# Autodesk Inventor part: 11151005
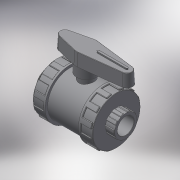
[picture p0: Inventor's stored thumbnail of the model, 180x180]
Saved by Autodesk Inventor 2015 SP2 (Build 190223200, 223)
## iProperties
Created: 2017-11
Part Number: 11151005
Material: Generic
Description: 2/NUT VALVE FEMALE THREAD 1/2" PVC
Document SubType Name: Modeling
Designer: KIM
Density: 1 g/cm^3
Appearance: Default
Author: KIM
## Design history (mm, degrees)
derived "111510.ipt"
feature "Solid1::111510.ipt"
tag "TaggingFeature1"
body "Solid1"
other parameters: "d0" = 75, "d1" = 18.631, "d2" = 45, "d3" = 15, "d4" = 14.9048, "d5" = 10.5, "d7" = 26.0834, "d8" = 40.5, "d13" = 0.55893, "d23" = 15, "d24" = 43.2, "d25" = 0.37262, "d26" = 0.55893, "d27" = 6.75, "d28" = 3.375, "d29" = 11.25, "d30" = 0, "d35" = 0.55893, "d39" = 22.5, "d45" = 360 deg, "d47" = 0.37262, "d50" = 24.75, "d51" = 13.5, "d53" = 0, "d55" = 3.7262, "d56" = 1.8631, "d57" = 10.5, "d58" = 0, "d59" = 0.55893, "d61" = 360 deg, "d63" = 18, "d64" = 45, "d66" = 65, "d68" = 9, "d69" = 19.5, "d70" = 11.25, "d71" = 3 deg, "d73" = 0.9, "d74" = 26, "d75" = 1.35, "d76" = 0, "d77" = 0.37262, "G_" = 18.631, "l_" = 15, "H_" = 75, "K_" = 45, "F_" = 45, "J_" = 65, "d67" = 18, "d72" = 4.5
